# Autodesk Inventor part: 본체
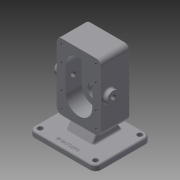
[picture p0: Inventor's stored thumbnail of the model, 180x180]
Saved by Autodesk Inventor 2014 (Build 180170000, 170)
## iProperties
Created: 2020-04
Part Number: 본체
Material: Generic
Document SubType Name: Modeling
Designer: kh
Density: 1 g/cm^3
Appearance: Default
Author: kh
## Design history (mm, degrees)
sketch "스케치1"
  geometry: L1 (-60, -50)-(60, -50); L2 (60, -50)-(60, 50); L3 (60, 50)-(-60, 50); L4 (-60, 50)-(-60, -50); L5 (-60, -50)-(60, 50); L6 (60, -50)-(-60, 50); 1 further point
  constraints: 12 end point, 2 midpoint, 2 parallel, 1 horizontal, 1 perpendicular
  dimensions: "d0" = 120 distance of L1.start L1.end; "d1" = 100 distance of L1.end L2.end
extrude "돌출1" new body sketch "스케치1" distance "d2" = 10; taper "d3" = 0 deg
node "작업 평면1"
sketch "스케치2"
  geometry: L1 (120, 10)-(0, 10) reference; L2 (20, 150)-(100, 150); L3 (100, 150)-(100, 30); L4 (100, 30)-(20, 30); L5 (20, 30)-(20, 150); L6 (20, 90)-(100, 90); 2 further points
  constraints: 10 end point, 3 midpoint, 2 parallel, 1 horizontal, 1 perpendicular, 1 vertical alignment
  dimensions: "d5" = 80 distance of L2.start L2.end; "d6" = 120 distance of L2.end L3.end; "d7" = 80 distance between parallel lines of L1 L6
extrude "돌출2" join sketch "스케치2" distance "d8" = 53; taper "d9" = 0 deg
sketch "스케치3"
  geometry: L1 (120, 0)-(0, 0) reference; C1 r 19 at (60, -112); 2 further points
  constraints: 1 centre point, 1 midpoint, 1 vertical alignment
  dimensions: "d10" = 38 diameter of C1; "d11" = 112 distance from line of C1.centre L1
extrude "돌출3" join sketch "스케치3" stored distance "d12" = 53; taper "d13" = 0 deg
sketch "스케치4"
  geometry: L1 (-24, 33)-(24, 33); L2 (24, 33)-(24, -20); L3 (24, -20)-(-24, -20); L4 (-24, -20)-(-24, 33); L5 (60, 50)-(-60, 50) reference; L6 (0, 33)-(0, -20); 1 further point
  constraints: 10 end point, 2 midpoint, 2 parallel, 1 horizontal, 1 perpendicular, 1 point on line
  dimensions: "d14" = 17 distance between parallel lines of L1 L5; "d15" = 53 distance between parallel lines of L3 L1; "d16" = 48 distance between parallel lines of L4 L2
extrude "돌출4" join sketch "스케치4" stored distance "d17" = 53; taper "d18" = 0 deg
sketch "스케치5"
  geometry: L1 (-20, 0)-(-20, 53) reference; L2 (0, 0)-(-20, 0) reference; L3 (0, 53)-(0, 0) reference; L4 (0, 53)-(-20, 53) reference; L5 (0, 0)-(-20, 11.547); L6 (0, 53)-(-20, 41.453); L7 (0, 70)-(0, -30) reference; L8 (-20, 11.547)-(-20, 0); L9 (0, 0)-(-20, 0); L10 (0, 53)-(-20, 53); L11 (-20, 41.453)-(-20, 53); 1 further point
  constraints: 12 end point, 2 collinear, 2 point on line, 1 parallel, 1 perpendicular
  dimensions: "d19" = 120 deg angle of L5 L7; "d20" = 120 deg angle of L7 L6
extrude "돌출5" cut sketch "스케치5" stored distance "d21" = 53; taper "d22" = 0 deg
sketch "스케치6"
  geometry: L1 (60, 112)-(60, 68); L2 (36, 112)-(36, 68); L3 (84, 68)-(84, 112); L4 (0, 0)-(120, 0) reference; A1 r 24 centre (60, 112) between (84, 112) and (36, 112); A2 r 24 centre (60, 68) between (36, 68) and (84, 68); 3 further points
  constraints: 8 end point, 4 point on circle, 4 tangent, 2 centre point, 2 midpoint, 1 parallel, 1 vertical, 1 vertical alignment
  dimensions: "d23" = 24 radius of A1; "d24" = 44 distance of L1.end L1.start; "d25" = 90 distance from line of point (60, 90) L4
extrude "돌출6" cut sketch "스케치6" distance "d26" = 29; taper "d27" = 0 deg
sketch "스케치7"
  geometry: L1 (36, 68)-(36, 112) reference; L2 (84, 112)-(84, 68) reference; C1 r 12.5 at (60, 112); C2 r 12.5 at (60, 68); A1 r 24 centre (60, 68) between (36, 68) and (84, 68) reference; A2 r 24 centre (60, 112) between (84, 112) and (36, 112) reference; 1 further point
  constraints: 2 centre point, 2 coincident
  dimensions: "d28" = 25 diameter of C1; "d29" = 25 diameter of C2
extrude "돌출7" cut sketch "스케치7" distance "d30" = 15; taper "d31" = 0 deg
sketch "스케치8"
  geometry: C1 r 19 at (0, 0) reference; C2 r 14 at (0, 0); 1 further point
  constraints: 1 centre point, 1 coincident
  dimensions: "d32" = 28 diameter of C2
extrude "돌출8" cut sketch "스케치8" distance "d33" = 7.3; taper "d34" = 0 deg
sketch "스케치9"
  geometry: C1 r 14 at (0, 0) reference; C2 r 8.5 at (0, 0); 1 further point
  constraints: 1 centre point, 1 coincident
  dimensions: "d35" = 17 diameter of C2
extrude "돌출9" cut sketch "스케치9" stored distance "d36" = 7.3; taper "d37" = 0 deg
fillet "모깎기1" dims "d38" = 9
sketch "스케치10"
  geometry: L1 (29, 39)-(91, 39); L2 (91, 39)-(91, 141); L3 (91, 141)-(29, 141); L4 (29, 141)-(29, 39); L5 (29, 112)-(91, 112); L6 (29, 68)-(91, 68); A1 r 9 centre (29, 141) between (29, 150) and (20, 141) reference; A2 r 9 centre (91, 141) between (100, 141) and (91, 150) reference; A3 r 9 centre (29, 39) between (20, 39) and (29, 30) reference; A4 r 9 centre (91, 39) between (91, 30) and (100, 39) reference; 9 further points
  constraints: 12 end point, 9 point on line, 8 coincident, 3 perpendicular, 2 parallel, 1 horizontal
  dimensions: "d39" = 29 distance between parallel lines of L5 L3; "d40" = 44 distance between parallel lines of L6 L5
hole "구멍1" sketch "스케치10" at (29, 141), (91, 141), (91, 112), (29, 112), (29, 68), (91, 68), (91, 39), (29, 39) diameter "d41" = 4.459; stored, may be unused: countersink angle "d45" = 90 deg, drill point angle "d47" = 118 deg; dims "d42" = 10, "d43" = 4, "d44" = 2, "d46" = 12
fillet "모깎기2" dims "d48" = 10
hole "구멍2" diameter "d51" = 9; stored, may be unused: countersink angle "d55" = 90 deg, drill point angle "d57" = 118 deg; dims "d49" = 10, "d50" = 10, "d52" = 10, "d53" = 4, "d54" = 2, "d56" = 12
node "작업 평면2"
sketch "스케치11"
  geometry: L1 (141, -73)-(141, 7) reference; L2 (102, -53)-(0, -53) reference; C1 r 11 at (51, -39); 1 further point
  constraints: 1 centre point
  dimensions: "d63" = 22 diameter of C1; "d64" = 90 distance from line of C1.centre L1; "d65" = 14 distance from line of C1.centre L2
extrude "돌출10" join sketch "스케치11" stored distance "d66" = 7.3; taper "d67" = 0 deg
hole "구멍3" diameter "d70" = 8.917; stored, may be unused: countersink angle "d74" = 90 deg, drill point angle "d76" = 118 deg; dims "d68" = 10, "d69" = 10, "d71" = 10, "d72" = 4, "d73" = 2, "d75" = 12
fillet "모깎기3" dims "d77" = 3
fillet "모깎기4" dims "d78" = 3
fillet "모깎기5" dims "d79" = 3
fillet "모깎기6" dims "d80" = 3
chamfer "모따기1" distance "d81" = 1; stored, may be unused: second distance "d82" = 2, angle "d83" = 45 deg
chamfer "모따기2" distance "d84" = 0.7; stored, may be unused: second distance "d85" = 2, angle "d86" = 30 deg
fillet "모깎기7" dims "d87" = 0.5
sketch "스케치12"
  geometry: L1 (-20.739, -36.998)-(20.739, -36.998); L2 (20.739, -36.998)-(20.739, -43.002); L3 (20.739, -43.002)-(-20.739, -43.002); L4 (-20.739, -43.002)-(-20.739, -36.998); L5 (-20.739, -43.002)-(20.739, -36.998); L6 (20.739, -43.002)-(-20.739, -36.998); L7 (-50, -50)-(50, -50) reference; L8 (-60, 40)-(-60, -40) reference; 2 further points
  constraints: 4 end point, 1 midpoint, 2 other
  dimensions: "d88" = 10 distance from line of point (0, -40) L7; "d89" = 60 distance from line of point (0, -40) L8
feature "엠보싱1" sketch "스케치12" dims "d0" = 120, "d1" = 100, "d90" = 0.5, "d91" = 0
node "솔리드1"
pattern_linear "직사각형 패턴1"
mirror "대칭1"
node "투영된 루프1"
node "투영된 루프2"
other parameters: "d4" = -17, "d62" = 8
